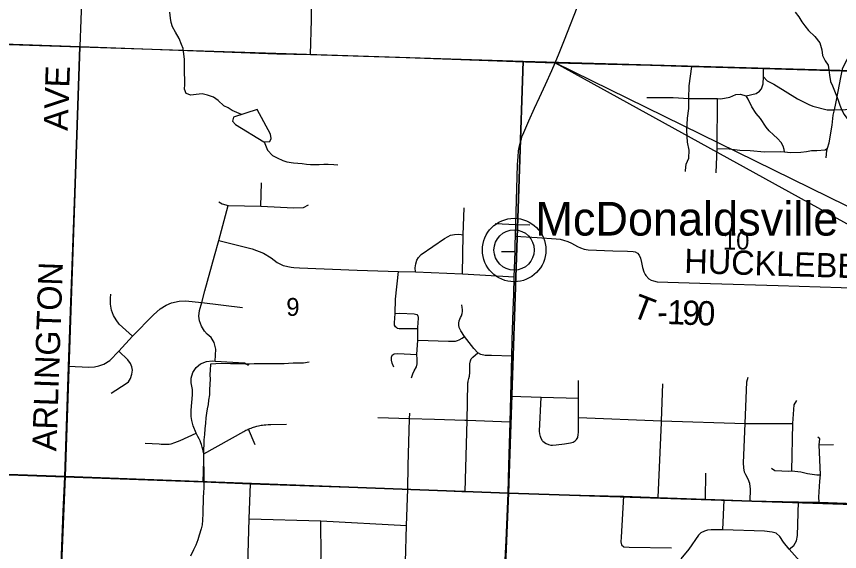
# Model space of a CAD drawing. Extents: x 0 to 34, y 0 to 22.
# Drawn here: x 5.169 to 7.099, y 18.784 to 20.038 of the extents above; entities that cross this region are included whole.
import ezdxf

# ---------------------------------------------------------------- set-up
doc = ezdxf.new("R2010")
doc.units = 0
for name, color, linetype in [('GM_X_Corporation', 7, 'Continuous'), ('GM_X_County_Road', 7, 'Continuous'), ('GM_X_Minor_Lake', 7, 'Continuous'), ('GM_X_Minor_River', 7, 'Continuous'), ('GM_X_Section_Text', 7, 'Continuous'), ('GM_X_State_Route', 7, 'Continuous'), ('GM_X_Township_Road', 7, 'Continuous'), ('GM_X_Township_Road_Text', 7, 'Continuous'), ('GM_X_Unincorporated', 7, 'Continuous'), ('GM_X_Unincorporated_Location', 7, 'Continuous'), ('GM_X_Unincorporated_Text', 7, 'Continuous'), ('SH_Text', 7, 'Continuous')]:
    doc.layers.add(name, color=color, linetype=linetype)

msp = doc.modelspace()

# ---------------------------------------------------------------- linework, layer by layer
at = {"layer": 'GM_X_Corporation'}
for points in [[(4.3035, 20.0005), (5.3173, 19.9675), (5.2829, 18.9603), (4.2642, 18.9963)], [(6.3571, 19.9339), (6.3228, 18.9214), (5.2829, 18.9603), (5.3173, 19.9675)], [(7.3757, 19.9046), (7.3448, 18.8879), (6.3228, 18.9214), (6.3571, 19.9339)], [(5.2829, 18.9603), (5.2412, 17.9526), (4.2238, 17.9879), (4.2642, 18.9963)], [(5.2829, 18.9603), (6.3228, 18.9214), (6.2808, 17.9117), (5.2412, 17.9526)], [(6.3228, 18.9214), (7.3448, 18.8879), (7.31, 17.8806), (6.2808, 17.9117)]]:
    msp.add_lwpolyline(points, close=True, dxfattribs=at)
at = {"layer": 'GM_X_County_Road'}
for points in [[(4.3055, 20.0023), (4.5632, 19.9931), (4.7721, 19.986), (4.8367, 19.9838), (4.937, 19.981), (5.3186, 19.9678)], [(5.3186, 19.9678), (5.5486, 19.9594), (5.7798, 19.9512), (5.8581, 19.9496), (6.0827, 19.9426), (6.3393, 19.933), (6.4321, 19.9298)], [(6.4321, 19.9298), (6.5564, 19.9268), (6.6553, 19.9245), (6.7524, 19.9212), (6.9208, 19.9164), (7.1049, 19.9107), (7.2267, 19.9074), (7.3719, 19.9057), (7.5522, 19.8996), (7.7083, 19.8943), (7.9987, 19.8856), (8.1128, 19.8831), (8.3105, 19.8769), (8.3538, 19.8762)], [(3.3299, 19.0351), (3.4202, 19.0314), (3.5515, 19.0261), (4.2655, 18.9966), (4.3563, 18.9933), (4.4885, 18.9883), (4.6568, 18.982), (4.7374, 18.979), (5.2825, 18.9592)], [(5.2825, 18.9592), (5.6064, 18.9477), (5.7174, 18.943), (6.0865, 18.9308), (6.2133, 18.9253)], [(6.2133, 18.9253), (6.2212, 18.925), (6.3217, 18.9214)], [(6.3217, 18.9214), (6.4273, 18.9177), (6.5886, 18.9143)], [(6.5886, 18.9143), (6.5925, 18.9142), (6.6737, 18.9111), (6.7848, 18.907), (6.8284, 18.9052), (6.8893, 18.9035), (7.0028, 18.9008), (7.0513, 18.8998), (7.2399, 18.8928), (7.3406, 18.8914)]]:
    msp.add_lwpolyline(points, dxfattribs=at)
at = {"layer": 'GM_X_Minor_Lake'}
for points in [[(5.733, 19.8206), (5.6775, 19.8025), (5.6753, 19.7929), (5.6822, 19.7854), (5.7487, 19.7448), (5.7631, 19.7457), (5.7664, 19.7522), (5.7644, 19.7628)], [(5.7644, 19.7628), (5.733, 19.8206)]]:
    msp.add_lwpolyline(points, dxfattribs=at)
at = {"layer": 'GM_X_Minor_River'}
for points in [[(5.6966, 19.8087), (5.675, 19.8184), (5.6651, 19.8243), (5.6552, 19.8292), (5.6418, 19.8411), (5.6307, 19.849), (5.6166, 19.8538), (5.604, 19.8567), (5.5904, 19.8557), (5.5779, 19.8541), (5.5672, 19.8581), (5.5633, 19.8683), (5.5636, 19.8793), (5.5638, 19.8923), (5.5633, 19.904), (5.5631, 19.9143), (5.5629, 19.9386), (5.5616, 19.9499), (5.5595, 19.9632), (5.556, 19.973), (5.5501, 19.987), (5.5416, 20.0017), (5.535, 20.0142), (5.5319, 20.024), (5.5298, 20.0346), (5.5289, 20.0483)], [(6.9947, 20.0486), (7.0032, 20.0373), (7.0105, 20.026), (7.0175, 20.0162), (7.0263, 20.0057), (7.0409, 19.9911), (7.0528, 19.9764), (7.0576, 19.9605), (7.0589, 19.9472), (7.0651, 19.9348), (7.0721, 19.9239), (7.0737, 19.9136), (7.075, 19.9011), (7.0774, 19.8863), (7.0821, 19.8758), (7.0868, 19.8644), (7.0919, 19.8523), (7.0954, 19.8425), (7.0994, 19.8304), (7.1044, 19.8187), (7.1099, 19.8085), (7.1272, 19.7851)], [(5.7495, 19.7449), (5.7577, 19.7248), (5.7692, 19.7124), (5.7799, 19.7068), (5.7936, 19.7009), (5.8031, 19.6976), (5.8183, 19.6955), (5.8286, 19.6949), (5.8388, 19.6935), (5.8487, 19.6924), (5.8585, 19.6918), (5.868, 19.6915), (5.879, 19.6913), (5.8893, 19.6922), (5.8999, 19.6919), (5.9132, 19.6913), (5.9226, 19.691)], [(5.8554, 19.2282), (5.8422, 19.2261), (5.832, 19.2256), (5.8179, 19.2259), (5.8066, 19.2253), (5.7963, 19.2241), (5.785, 19.224), (5.7751, 19.2246), (5.7592, 19.224), (5.749, 19.2243), (5.7262, 19.224), (5.7152, 19.2235), (5.7057, 19.2234), (5.694, 19.224), (5.6834, 19.2239), (5.6712, 19.2245), (5.6583, 19.2248), (5.6363, 19.2245), (5.6238, 19.2232), (5.6229, 19.2092), (5.6226, 19.1989), (5.6228, 19.1875), (5.6221, 19.1773), (5.6219, 19.1628), (5.6213, 19.1518), (5.6196, 19.1393), (5.6182, 19.129), (5.6164, 19.1187), (5.6146, 19.1085), (5.6129, 19.0974), (5.6119, 19.0849), (5.6109, 19.072), (5.6095, 19.0587), (5.6086, 19.0461), (5.6079, 19.0347), (5.6077, 19.0245), (5.6074, 19.0131), (5.6077, 18.9884), (5.6082, 18.9789), (5.6086, 18.9478), (5.608, 18.9333), (5.6078, 18.9223), (5.6071, 18.9113), (5.6065, 18.8988), (5.6059, 18.887), (5.6061, 18.8737), (5.6048, 18.8578), (5.6041, 18.8471), (5.602, 18.8372), (5.5976, 18.8227), (5.5939, 18.8117), (5.5892, 18.7995), (5.5844, 18.788), (5.5774, 18.7732)]]:
    msp.add_lwpolyline(points, dxfattribs=at)
at = {"layer": 'GM_X_State_Route'}
for points in [[(6.3217, 18.9214), (6.3238, 18.9861), (6.3252, 19.0377), (6.3265, 19.0879), (6.328, 19.1484), (6.3306, 19.2422), (6.3316, 19.2799), (6.3339, 19.3512), (6.3353, 19.3864), (6.3362, 19.428), (6.338, 19.4874), (6.3383, 19.5054), (6.3389, 19.5234), (6.3396, 19.5509), (6.3415, 19.608), (6.3432, 19.6623), (6.344, 19.6917), (6.345, 19.7092), (6.3464, 19.7231), (6.3475, 19.731), (6.3491, 19.7381), (6.3507, 19.7445), (6.3528, 19.7514), (6.3549, 19.7575), (6.3582, 19.7661), (6.3632, 19.7776), (6.3704, 19.7938), (6.3839, 19.8234), (6.3954, 19.8482), (6.4095, 19.879), (6.4242, 19.9117), (6.4321, 19.9298), (6.4418, 19.9526), (6.454, 19.9834), (6.4904, 20.0779)], [(6.3132, 18.7351), (6.3169, 18.8101), (6.3196, 18.8663), (6.3217, 18.9214)]]:
    msp.add_lwpolyline(points, dxfattribs=at)
at = {"layer": 'GM_X_Township_Road'}
for p, q in [((6.9209, 19.897), (6.9208, 19.9164)), ((5.7421, 19.5937), (5.7433, 19.6486)), ((6.306, 19.4877), (6.338, 19.4874)), ((7.0514, 19.0342), (7.0843, 19.0348)), ((6.7848, 18.907), (6.7853, 18.9678)), ((6.8251, 18.8354), (6.8284, 18.9052))]:
    msp.add_line(p, q, dxfattribs=at)
for points in [[(5.3186, 19.9678), (5.3252, 20.1567), (5.3321, 20.3523), (5.3348, 20.3921), (5.3386, 20.5284), (5.341, 20.5916), (5.344, 20.6436), (5.3482, 20.7817), (5.3499, 20.7982), (5.3529, 20.8084), (5.3573, 20.8173), (5.3696, 20.8421), (5.3739, 20.8537), (5.3772, 20.8695), (5.3782, 20.8837), (5.3788, 20.8988), (5.3795, 20.9204)], [(5.8581, 19.9496), (5.8607, 20.0309), (5.8609, 20.0605), (5.8616, 20.0752), (5.8637, 20.0852), (5.8674, 20.0977), (5.8689, 20.1083), (5.8685, 20.1168), (5.8667, 20.1282), (5.8635, 20.1419), (5.8631, 20.152), (5.8631, 20.1642), (5.8646, 20.1923), (5.867, 20.2851), (5.8674, 20.3022), (5.8689, 20.31), (5.8709, 20.3163), (5.8745, 20.323), (5.8795, 20.3308)], [(7.0674, 19.7074), (7.0689, 19.7239), (7.0706, 19.7298), (7.0742, 19.7426), (7.0817, 19.7837), (7.0839, 19.8068), (7.0867, 19.8198), (7.0899, 19.8345), (7.0959, 19.8629), (7.1019, 19.8951), (7.1049, 19.9107), (7.1056, 19.9145), (7.106, 19.9153), (7.1131, 19.9309), (7.1213, 19.9459), (7.1288, 19.9661), (7.1288, 19.9818), (7.1298, 19.994), (7.1326, 20.0296)], [(5.235, 17.686), (5.2348, 17.7232), (5.2396, 17.8514), (5.2414, 17.8989), (5.2456, 17.9948), (5.2499, 18.103), (5.2537, 18.2087), (5.2631, 18.4401), (5.266, 18.5391), (5.271, 18.6683), (5.2746, 18.7763), (5.2788, 18.8778), (5.2825, 18.9592), (5.2862, 19.0782), (5.29, 19.1939), (5.291, 19.2186), (5.3186, 19.9678)], [(6.7379, 19.6748), (6.7379, 19.6777), (6.7393, 19.6921), (6.7451, 19.7064), (6.7465, 19.7251), (6.7422, 19.7438), (6.7408, 19.7711), (6.7423, 19.7999), (6.7452, 19.8229), (6.7452, 19.8415), (6.7454, 19.8463), (6.7466, 19.876), (6.7524, 19.9212)], [(6.8801, 19.8525), (6.903, 19.8579), (6.9112, 19.8634), (6.9157, 19.8686), (6.9198, 19.8809), (6.9209, 19.897)], [(6.9209, 19.897), (6.9291, 19.8875), (6.9449, 19.8795), (6.9715, 19.863), (7.0003, 19.845), (7.0268, 19.8321), (7.0362, 19.8278), (7.0699, 19.8199), (7.0867, 19.8198), (7.1131, 19.8206), (7.1411, 19.822), (7.1713, 19.8213), (7.1928, 19.8176), (7.2101, 19.8183), (7.2222, 19.8175)], [(6.6467, 19.8484), (6.7085, 19.8484), (6.7454, 19.8463), (6.8005, 19.8462), (6.8127, 19.8458), (6.8206, 19.8455), (6.8416, 19.8492), (6.8559, 19.8557), (6.8659, 19.8566), (6.8801, 19.8525)], [(6.8095, 19.6723), (6.812, 19.7287), (6.8127, 19.8458)], [(6.9699, 19.7209), (6.9693, 19.7265), (6.9668, 19.7344), (6.9618, 19.743), (6.9532, 19.7527), (6.9438, 19.761), (6.9341, 19.77), (6.9266, 19.7793), (6.9137, 19.7994), (6.9036, 19.8109), (6.8932, 19.8264), (6.8849, 19.8447), (6.8801, 19.8525)], [(6.812, 19.7287), (6.8403, 19.728), (6.8648, 19.7251), (6.8895, 19.724), (6.9226, 19.7215), (6.96, 19.7218), (6.9699, 19.7209), (6.984, 19.7196), (7.0078, 19.7204), (7.0211, 19.7221), (7.0329, 19.7246), (7.0458, 19.7243), (7.0652, 19.7261), (7.0706, 19.7298)], [(5.6351, 19.2308), (5.6364, 19.2584), (5.6322, 19.2745), (5.6252, 19.2857), (5.6164, 19.2939), (5.6098, 19.3008), (5.6026, 19.3128), (5.5984, 19.3253), (5.5968, 19.3361), (5.5983, 19.3491), (5.6034, 19.368), (5.6109, 19.3957), (5.6335, 19.4777), (5.6438, 19.5136), (5.6651, 19.5953)], [(5.6438, 19.604), (5.6513, 19.5989), (5.6651, 19.5953), (5.7421, 19.5937), (5.8195, 19.5902), (5.842, 19.5906), (5.8535, 19.5973)], [(6.2147, 19.4354), (6.216, 19.5265), (6.2187, 19.5899)], [(6.2915, 19.5529), (6.3396, 19.5509), (6.3724, 19.5502)], [(5.6438, 19.5136), (5.7216, 19.4934), (5.7484, 19.4835), (5.7658, 19.4725), (5.7804, 19.4614), (5.7946, 19.4551), (5.8132, 19.4508), (5.8193, 19.4504)], [(6.1047, 19.4401), (6.1037, 19.4493), (6.1054, 19.4588), (6.1079, 19.4671), (6.1114, 19.4738), (6.1177, 19.4806), (6.1724, 19.5177), (6.1811, 19.523), (6.1866, 19.5255), (6.1959, 19.5275), (6.2044, 19.528), (6.2115, 19.527), (6.216, 19.5265)], [(6.3389, 19.5234), (6.3902, 19.5202), (6.4346, 19.5174), (6.4435, 19.5161), (6.4516, 19.5143), (6.4621, 19.5106), (6.4701, 19.5072), (6.4844, 19.4991), (6.4912, 19.4962), (6.4999, 19.4932), (6.5093, 19.4914), (6.5676, 19.4893), (6.6013, 19.4881), (6.6148, 19.4876), (6.6194, 19.487), (6.6253, 19.4837), (6.6293, 19.4789), (6.6324, 19.4722), (6.6345, 19.4621), (6.6367, 19.45), (6.6398, 19.4399), (6.643, 19.4336), (6.6444, 19.4312), (6.6516, 19.4237), (6.6574, 19.4204), (6.6625, 19.4184), (6.6712, 19.4168), (6.796, 19.4128), (6.9549, 19.408), (7.25, 19.3984)], [(5.8193, 19.4504), (5.8325, 19.4496), (5.968, 19.4441), (6.0647, 19.4409), (6.1047, 19.4401), (6.2147, 19.4354), (6.3362, 19.428)], [(6.0614, 19.3077), (6.0576, 19.3107), (6.0557, 19.3147), (6.0553, 19.3206), (6.0568, 19.3424), (6.0576, 19.3756), (6.0647, 19.4409)], [(5.4413, 19.2888), (5.4099, 19.3176), (5.4025, 19.3271), (5.3964, 19.3378), (5.392, 19.3503), (5.3895, 19.3639), (5.3893, 19.3779), (5.3901, 19.3874)], [(5.291, 19.2186), (5.3384, 19.2166), (5.3518, 19.2173), (5.3624, 19.2193), (5.3735, 19.2235), (5.3878, 19.2324), (5.4089, 19.2539), (5.4413, 19.2888), (5.4899, 19.3391), (5.5056, 19.3529), (5.5197, 19.3616), (5.5327, 19.3671), (5.5503, 19.3713), (5.5656, 19.3718), (5.6034, 19.368), (5.6986, 19.3564)], [(6.3306, 19.2422), (6.2831, 19.2434), (6.268, 19.2439), (6.2579, 19.2464), (6.2509, 19.2502), (6.2417, 19.2604), (6.2193, 19.2885), (6.2105, 19.3017), (6.2072, 19.3092), (6.2059, 19.3147), (6.2059, 19.3193), (6.207, 19.325), (6.2102, 19.3328), (6.2126, 19.3369), (6.214, 19.342), (6.2148, 19.3472), (6.2145, 19.3518), (6.214, 19.3564), (6.2129, 19.3623)], [(6.0568, 19.3424), (6.0675, 19.3428), (6.1012, 19.3411), (6.1049, 19.3407), (6.1077, 19.3396), (6.1104, 19.3371)], [(6.095, 19.1914), (6.0986, 19.2009), (6.1018, 19.2077), (6.1069, 19.2174), (6.1086, 19.2242), (6.1086, 19.2353), (6.108, 19.2463), (6.11, 19.28), (6.1099, 19.3071), (6.1112, 19.3227), (6.1116, 19.3293), (6.1116, 19.3336), (6.1104, 19.3371)], [(6.0614, 19.3077), (6.0659, 19.3068), (6.0871, 19.3072), (6.0982, 19.3074), (6.1099, 19.3071)], [(6.11, 19.28), (6.1818, 19.2776), (6.1927, 19.2772), (6.198, 19.2776), (6.203, 19.2789), (6.2071, 19.2805), (6.214, 19.2845), (6.2193, 19.2885)], [(5.3908, 19.1558), (5.4262, 19.178), (5.4314, 19.1824), (5.4365, 19.1897), (5.4398, 19.1999), (5.4408, 19.2094), (5.4396, 19.217), (5.4365, 19.2252), (5.4304, 19.2334), (5.4089, 19.2539)], [(6.0539, 19.2161), (6.0501, 19.2261), (6.0485, 19.2328), (6.0485, 19.2396), (6.0501, 19.2447), (6.0544, 19.248), (6.0628, 19.2485), (6.108, 19.2463)], [(6.2212, 18.925), (6.226, 19.0911), (6.2272, 19.1778), (6.2274, 19.1795), (6.2278, 19.1819), (6.2281, 19.1833), (6.2295, 19.1895), (6.2314, 19.1952), (6.232, 19.2042), (6.232, 19.2245), (6.2333, 19.2315), (6.2352, 19.2358), (6.2393, 19.2399), (6.2509, 19.2502)], [(5.6064, 18.9477), (5.6079, 18.9974), (5.6082, 19.0135), (5.607, 19.0199), (5.606, 19.0245), (5.6045, 19.0293), (5.6029, 19.0348), (5.6014, 19.0392), (5.5994, 19.044), (5.5974, 19.0486), (5.5946, 19.0543), (5.59, 19.062), (5.5835, 19.079), (5.5798, 19.0918), (5.5786, 19.1006), (5.5785, 19.1079), (5.5786, 19.1154), (5.5818, 19.1515), (5.5815, 19.164), (5.5789, 19.1795), (5.5786, 19.191), (5.5822, 19.2038), (5.5901, 19.2153), (5.6006, 19.2239), (5.6147, 19.2294), (5.6282, 19.2311), (5.6351, 19.2308), (5.7035, 19.2268), (5.713, 19.2212)], [(6.4026, 19.0441), (6.4069, 19.0401), (6.411, 19.0374), (6.4167, 19.035), (6.4215, 19.0339), (6.4259, 19.0337), (6.4347, 19.0343), (6.4543, 19.0365), (6.4683, 19.0391), (6.4742, 19.041), (6.4787, 19.0439), (6.4822, 19.047), (6.4849, 19.0518), (6.4862, 19.0584), (6.4864, 19.063), (6.4866, 19.0982), (6.4871, 19.1437), (6.4871, 19.1851)], [(6.8893, 18.9035), (6.8898, 18.9307), (6.8886, 18.9436), (6.8846, 18.954), (6.8794, 18.9638), (6.8763, 18.97), (6.8742, 18.9804), (6.8735, 18.9923), (6.8742, 19.0098), (6.8778, 19.0843), (6.8815, 19.182), (6.8846, 19.1931)], [(6.6737, 18.9111), (6.681, 19.0871), (6.6811, 19.0903), (6.6841, 19.1774)], [(6.328, 19.1484), (6.3991, 19.1464), (6.4871, 19.1437)], [(6.4026, 19.0441), (6.3995, 19.0494), (6.3974, 19.0542), (6.3963, 19.0598), (6.3957, 19.0662), (6.3991, 19.1464)], [(6.9869, 18.9733), (6.9894, 19.0846), (6.9921, 19.1284), (6.9986, 19.1382)], [(6.0778, 18.6083), (6.0787, 18.6416), (6.0808, 18.7592), (6.0836, 18.845), (6.0865, 18.9308), (6.0877, 18.9861), (6.0908, 19.0955), (6.0909, 19.1087)], [(6.2202, 19.0913), (6.1489, 19.0939), (6.0908, 19.0955), (6.0165, 19.098)], [(6.3265, 19.0879), (6.226, 19.0911), (6.2202, 19.0913)], [(6.4866, 19.0982), (6.6811, 19.0903), (6.8778, 19.0843), (6.9894, 19.0846)], [(5.6082, 19.0135), (5.7017, 19.0657), (5.7041, 19.067), (5.7071, 19.0685), (5.7101, 19.0699), (5.7129, 19.0712), (5.7163, 19.0726), (5.7192, 19.0737), (5.7222, 19.0748), (5.7248, 19.0756), (5.7276, 19.0765), (5.7302, 19.0772), (5.7329, 19.078), (5.7361, 19.0788), (5.7394, 19.0795), (5.7427, 19.0801), (5.7459, 19.0806), (5.7498, 19.0812), (5.7535, 19.0816), (5.7592, 19.0821), (5.7624, 19.0822), (5.7654, 19.0823), (5.8019, 19.0829)], [(5.7285, 19.0346), (5.7129, 19.0712), (5.7127, 19.0719)], [(5.4706, 19.0383), (5.5034, 19.0366), (5.5082, 19.0361), (5.5116, 19.0361), (5.5147, 19.0358), (5.5197, 19.0356), (5.523, 19.0358), (5.5267, 19.0362), (5.5315, 19.0369), (5.5404, 19.0395), (5.5526, 19.0446), (5.59, 19.062)], [(7.0513, 18.8998), (7.0502, 18.9114), (7.0526, 18.949), (7.0543, 18.9638), (7.0514, 19.0342), (7.0527, 19.0488), (7.0476, 19.0527)], [(6.9394, 18.9795), (6.9474, 18.9742), (6.9802, 18.9724), (6.9869, 18.9733), (7.0084, 18.9709), (7.024, 18.9669), (7.0458, 18.9641), (7.0543, 18.9638)], [(5.7213, 18.6607), (5.7144, 18.675), (5.7102, 18.6865), (5.7102, 18.7023), (5.7112, 18.7546), (5.712, 18.7789), (5.7147, 18.8608), (5.7174, 18.943)], [(6.5925, 18.9142), (6.5871, 18.8176), (6.5862, 18.8067), (6.5874, 18.7997), (6.5929, 18.7955), (6.6056, 18.7948), (6.7052, 18.7927)], [(6.9808, 18.7898), (6.9917, 18.7987), (6.9977, 18.8091), (7.0004, 18.8216), (7.0028, 18.9008)], [(5.7147, 18.8608), (5.8827, 18.8565), (6.0836, 18.845)], [(5.885, 18.6243), (5.8725, 18.6501), (5.8835, 18.7717), (5.8827, 18.8565)], [(7.0253, 18.7401), (6.9808, 18.7898), (6.9676, 18.806), (6.9587, 18.8195), (6.9502, 18.8271), (6.941, 18.8299), (6.9226, 18.8317), (6.8251, 18.8354), (6.7978, 18.8354), (6.7896, 18.8345), (6.7819, 18.8324), (6.7739, 18.8281), (6.7681, 18.8229), (6.7451, 18.7901), (6.7265, 18.7673)]]:
    msp.add_lwpolyline(points, dxfattribs=at)
at = {"layer": 'GM_X_Unincorporated'}
for radius in [0.0744, 0.0472]:
    msp.add_circle((6.3358, 19.491), radius, dxfattribs=at)
at = {"layer": 'GM_X_Unincorporated_Location'}
msp.add_line((6.3358, 19.491), (6.3358, 19.491), dxfattribs=at)
at = {"layer": 'SH_Text'}
msp.add_lwpolyline([(10.6613, 17.855), (6.4321, 19.9298), (10.6613, 17.5984)], close=True, dxfattribs=at)

# ---------------------------------------------------------------- texts
at = {"layer": 'GM_X_Section_Text'}
for s, height, p in [('10', 0.04186, (6.8253, 19.4921)), ('9', 0.0419, (5.8016, 19.3367))]:
    msp.add_text(s, height=height, rotation=0, dxfattribs=at).set_placement(p)
at = {"layer": 'GM_X_Township_Road_Text'}
for s, height, rotation, p in [('AVE', 0.05682, 87.9903, (5.2892, 19.7699)), ('HUCKLEBERRY', 0.056818, 358.2362, (6.7343, 19.4373)), ('ARLINGTON', 0.05682, 88.0007, (5.2625, 19.0188)), ('T', 0.0568, 338.9093, (6.6081, 19.3364)), ('1', 0.0568, 357.8034, (6.694, 19.3176)), ('9', 0.0568, 358.0891, (6.7293, 19.3162)), ('0', 0.0568, 358.1737, (6.7644, 19.3151)), ('-', 0.0568, 1.465, (6.6716, 19.317))]:
    msp.add_text(s, height=height, rotation=rotation, dxfattribs=at).set_placement(p)
at = {"layer": 'GM_X_Unincorporated_Text'}
msp.add_text('McDonaldsville', height=0.078977, rotation=0, dxfattribs=at).set_placement((6.3857, 19.5249))

doc.saveas('drawing.dxf')
